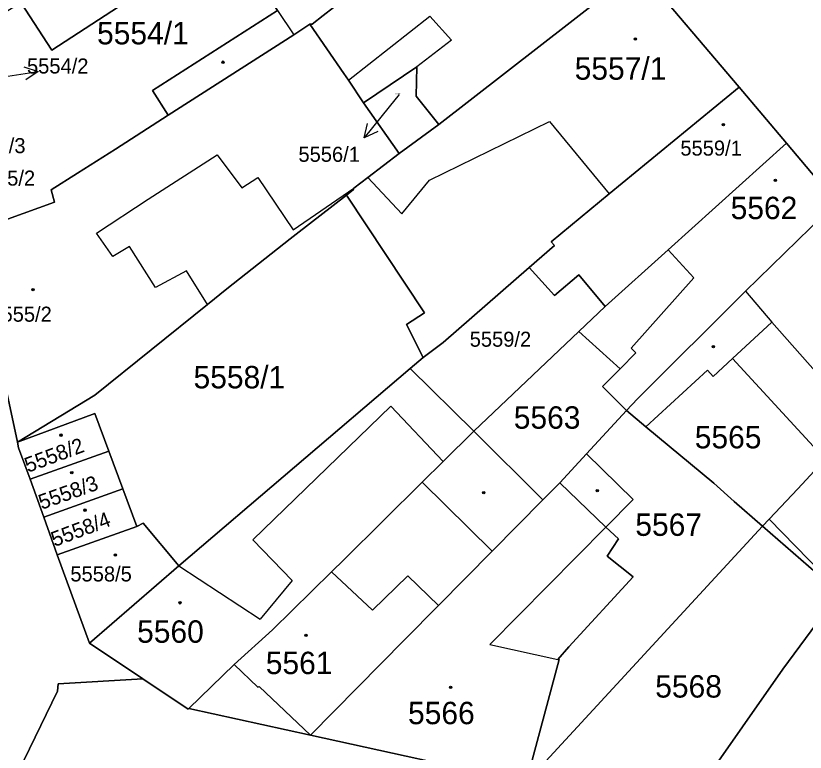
# Model space of a CAD drawing. Extents: x -596233 to -595156, y -1161235 to -1159375.
# Drawn here: x -595353.5 to -595293.6, y -1160883.5 to -1160827.6 of the extents above; entities that cross this region are included whole.
import ezdxf

# ---------------------------------------------------------------- set-up
doc = ezdxf.new("R2010")
doc.units = 0
for name, color, linetype in [('KN_CAR_KR', 7, 'Continuous'), ('KN_KULTURY', 7, 'Continuous'), ('KN_PARC_CIS_POM', 7, 'Continuous'), ('KN_PARC_CIS_POZ', 7, 'Continuous'), ('KN_PARC_CIS_STAV', 7, 'Continuous'), ('KN_PARC_PLOCHA', 7, 'Continuous'), ('PARC_C_SIPKA', 7, 'Continuous'), ('parcely_l', 7, 'Continuous')]:
    doc.layers.add(name, color=color, linetype=linetype)

msp = doc.modelspace()

# ---------------------------------------------------------------- linework, layer by layer
at = {"layer": 'KN_CAR_KR'}
for points in [[(-595333.66, -1160827.23), (-595332.43, -1160829.08)], [(-595328.27, -1160832.53), (-595322.1, -1160827.67)], [(-595322.1, -1160827.67), (-595320.45, -1160829.49)], [(-595320.45, -1160829.49), (-595323.08, -1160831.51)], [(-595322.13, -1160840.12), (-595313.02, -1160835.65)], [(-595313.02, -1160835.65), (-595308.5, -1160841.15)], [(-595343.48, -1160841.56), (-595338.23, -1160838.19)], [(-595338.23, -1160838.19), (-595336.37, -1160840.7)], [(-595336.37, -1160840.7), (-595335.14, -1160839.92)], [(-595335.14, -1160839.92), (-595332.46, -1160843.88)], [(-595326.81, -1160839.91), (-595324.22, -1160842.67)], [(-595324.22, -1160842.67), (-595322.13, -1160840.12)], [(-595332.46, -1160843.88), (-595327.86, -1160840.71)], [(-595347.39, -1160844.14), (-595343.48, -1160841.56)], [(-595346.15, -1160845.91), (-595347.39, -1160844.14)], [(-595344.88, -1160845.15), (-595346.15, -1160845.91)], [(-595342.9, -1160848.26), (-595344.88, -1160845.15)], [(-595304.02, -1160845.39), (-595302.09, -1160847.53)], [(-595340.57, -1160847), (-595342.9, -1160848.26)], [(-595338.98, -1160849.55), (-595340.57, -1160847)], [(-595302.09, -1160847.53), (-595306.84, -1160852.85)], [(-595298.16, -1160848.54), (-595296.15, -1160850.89)], [(-595299.15, -1160853.65), (-595296.15, -1160850.89)], [(-595296.15, -1160850.89), (-595289.59, -1160858.31)], [(-595307.67, -1160854.42), (-595306.47, -1160853.22)], [(-595306.47, -1160853.22), (-595306.84, -1160852.85)], [(-595325.05, -1160857.26), (-595335.54, -1160867.4)], [(-595321.09, -1160861.45), (-595325.05, -1160857.26)], [(-595322.68, -1160863.02), (-595317.37, -1160868.26)], [(-595312.24, -1160863.07), (-595308.76, -1160866.45)], [(-595291.37, -1160870.97), (-595296.37, -1160865.83)], [(-595308.76, -1160866.45), (-595317.56, -1160875.35)], [(-595335.54, -1160867.4), (-595332.54, -1160870.48)], [(-595341.13, -1160869.37), (-595334.97, -1160873.42)], [(-595329.55, -1160869.83), (-595326.44, -1160872.74)], [(-595326.44, -1160872.74), (-595323.76, -1160870.12)], [(-595323.76, -1160870.12), (-595321.44, -1160872.39)], [(-595332.54, -1160870.48), (-595334.97, -1160873.42)], [(-595317.56, -1160875.35), (-595312.39, -1160876.47)], [(-595336.95, -1160876.86), (-595335.15, -1160878.58)], [(-595335.15, -1160878.58), (-595335.06, -1160878.54)], [(-595331.16, -1160882.23), (-595335.06, -1160878.54)]]:
    msp.add_lwpolyline(points, dxfattribs=at)
at = {"layer": 'KN_KULTURY'}
for centre, radius in [((-595306.51, -1160829.41), 0.09), ((-595306.51, -1160829.41), 0.0398), ((-595337.8, -1160831.16), 0.09), ((-595337.8, -1160831.16), 0.0398), ((-595299.84, -1160835.91), 0.09), ((-595299.84, -1160835.91), 0.0398), ((-595295.89, -1160840.12), 0.09), ((-595295.89, -1160840.12), 0.0398), ((-595352.2, -1160848.42), 0.09), ((-595352.2, -1160848.42), 0.0398), ((-595300.59, -1160852.75), 0.09), ((-595300.59, -1160852.75), 0.0398), ((-595350.09, -1160859.46), 0.09), ((-595350.09, -1160859.46), 0.0398), ((-595349.26, -1160862.31), 0.09), ((-595349.26, -1160862.31), 0.0398), ((-595309.4, -1160863.66), 0.09), ((-595318.02, -1160863.82), 0.09), ((-595318.02, -1160863.82), 0.0398), ((-595309.4, -1160863.66), 0.0398), ((-595348.26, -1160865.15), 0.09), ((-595348.26, -1160865.15), 0.0398), ((-595345.95, -1160868.56), 0.09), ((-595345.95, -1160868.56), 0.0398), ((-595341.06, -1160872.18), 0.09), ((-595341.06, -1160872.18), 0.0398), ((-595331.5, -1160874.64), 0.09), ((-595331.5, -1160874.64), 0.0398), ((-595320.53, -1160878.59), 0.09), ((-595320.53, -1160878.59), 0.0398)]:
    msp.add_circle(centre, radius, dxfattribs=at)
at = {"layer": 'KN_PARC_PLOCHA'}
for points in [[(-595291.25, -1160841.8), (-595295.06, -1160837.3), (-595298.65, -1160833.06), (-595306.24, -1160824.08), (-595306.08, -1160823.95), (-595309.1, -1160820.28), (-595309.22, -1160820.38), (-595313.94, -1160814.7), (-595321.78, -1160805.34), (-595321.74, -1160805.3), (-595325.72, -1160800.55), (-595329.4, -1160796.16)], [(-595356.82, -1160844.02), (-595353.39, -1160859.98), (-595353.3, -1160860.42), (-595352.43, -1160862.81), (-595351.39, -1160865.67), (-595350.36, -1160868.53), (-595347.92, -1160875.23), (-595343.87, -1160877.94), (-595350.29, -1160878.33), (-595350.35, -1160878.88), (-595354.16, -1160886.75)], [(-595304.34, -1160890.08), (-595295.32, -1160877.21), (-595291.9, -1160872.55), (-595291.03, -1160871.54), (-595292.81, -1160869.91), (-595296.88, -1160866.37), (-595296.37, -1160865.83), (-595294.19, -1160863.52), (-595292.63, -1160861.84), (-595292.13, -1160861.26), (-595289.59, -1160858.31), (-595289.41, -1160858.1), (-595283.5, -1160850.97), (-595273.06, -1160862.41), (-595279.19, -1160870.73), (-595279.95, -1160871.75), (-595280.08, -1160871.93), (-595280.97, -1160873.16), (-595286.71, -1160881.05), (-595285, -1160882.13), (-595283.05, -1160883.35), (-595279.41, -1160885.64)], [(-595354.16, -1160886.75), (-595350.35, -1160878.88), (-595350.29, -1160878.33), (-595343.87, -1160877.94), (-595340.44, -1160880.24), (-595340.39, -1160880.2), (-595331.16, -1160882.23), (-595314.8, -1160885.82)]]:
    msp.add_lwpolyline(points, dxfattribs=at)
for points in [[(-595313.94, -1160814.7), (-595323.88, -1160822.8), (-595323.92, -1160822.74), (-595330.19, -1160827.61), (-595331.03, -1160828.27), (-595331.2, -1160828.28), (-595332.43, -1160829.08), (-595341.94, -1160835.18), (-595343.14, -1160833.31), (-595333.66, -1160827.23), (-595337.44, -1160821.55), (-595343.7, -1160825.62), (-595350.77, -1160830.25), (-595353.13, -1160826.63), (-595345.95, -1160822.04), (-595341.6, -1160819.19), (-595334.72, -1160814.69), (-595334.18, -1160814.3), (-595321.78, -1160805.34)], [(-595306.24, -1160824.08), (-595321.42, -1160835.9), (-595323.14, -1160833.75), (-595323.08, -1160831.51), (-595327.13, -1160834.25), (-595328.27, -1160832.53), (-595328.63, -1160832.01), (-595331.2, -1160828.28), (-595331.03, -1160828.27), (-595330.19, -1160827.61), (-595323.92, -1160822.74), (-595323.88, -1160822.8), (-595313.94, -1160814.7), (-595309.22, -1160820.38), (-595309.1, -1160820.28), (-595306.08, -1160823.95)], [(-595341.94, -1160835.18), (-595345.95, -1160837.75), (-595348.84, -1160839.59), (-595350.83, -1160840.85), (-595350.57, -1160841.77), (-595356.82, -1160844.02), (-595358.27, -1160844.17), (-595358.76, -1160839.37), (-595358.9, -1160835.71), (-595354.54, -1160835.03), (-595354.26, -1160834.39), (-595355.07, -1160830.1), (-595360.09, -1160831.28), (-595360.11, -1160830.94), (-595353.13, -1160826.63), (-595350.77, -1160830.25), (-595343.7, -1160825.62), (-595337.44, -1160821.55), (-595333.66, -1160827.23), (-595343.14, -1160833.31)], [(-595298.65, -1160833.06), (-595308.5, -1160841.15), (-595312.89, -1160844.78), (-595312.65, -1160845.07), (-595314.57, -1160846.74), (-595321.09, -1160852.43), (-595322.61, -1160853.56), (-595323.87, -1160851.07), (-595322.52, -1160850.18), (-595328.43, -1160841.24), (-595327.9, -1160840.83), (-595327.86, -1160840.71), (-595326.81, -1160839.91), (-595324.43, -1160838.08), (-595321.42, -1160835.9), (-595306.24, -1160824.08)], [(-595327.13, -1160834.25), (-595324.43, -1160838.08), (-595326.81, -1160839.91), (-595327.86, -1160840.71), (-595327.9, -1160840.83), (-595328.43, -1160841.24), (-595332.24, -1160844.2), (-595332.7, -1160844.56), (-595337.5, -1160848.36), (-595338.98, -1160849.55), (-595347.51, -1160856.42), (-595353.39, -1160859.98), (-595356.82, -1160844.02), (-595350.57, -1160841.77), (-595350.83, -1160840.85), (-595348.84, -1160839.59), (-595345.95, -1160837.75), (-595341.94, -1160835.18), (-595332.43, -1160829.08), (-595331.2, -1160828.28), (-595328.63, -1160832.01), (-595328.27, -1160832.53)], [(-595321.42, -1160835.9), (-595324.43, -1160838.08), (-595327.13, -1160834.25), (-595323.08, -1160831.51), (-595323.14, -1160833.75)], [(-595295.06, -1160837.3), (-595304.02, -1160845.39), (-595308.81, -1160849.71), (-595310.81, -1160847.29), (-595312.65, -1160848.87), (-595314.57, -1160846.74), (-595312.65, -1160845.07), (-595312.89, -1160844.78), (-595308.5, -1160841.15), (-595298.65, -1160833.06)], [(-595291.25, -1160841.8), (-595298.16, -1160848.54), (-595306.36, -1160856.71), (-595307.18, -1160857.59), (-595309.01, -1160855.77), (-595307.67, -1160854.42), (-595310.8, -1160851.6), (-595308.81, -1160849.71), (-595304.02, -1160845.39), (-595295.06, -1160837.3)], [(-595322.61, -1160853.56), (-595323.6, -1160854.4), (-595341.13, -1160869.37), (-595343.86, -1160866.13), (-595344.34, -1160866.4), (-595345.39, -1160863.54), (-595346.45, -1160860.67), (-595347.51, -1160857.81), (-595353.39, -1160859.98), (-595347.51, -1160856.42), (-595338.98, -1160849.55), (-595337.5, -1160848.36), (-595332.7, -1160844.56), (-595332.24, -1160844.2), (-595328.43, -1160841.24), (-595322.52, -1160850.18), (-595323.87, -1160851.07)], [(-595283.5, -1160850.97), (-595289.41, -1160858.1), (-595289.59, -1160858.31), (-595292.13, -1160861.26), (-595299.15, -1160853.65), (-595300.61, -1160855), (-595301.04, -1160854.53), (-595305.72, -1160858.84), (-595307.18, -1160857.59), (-595306.36, -1160856.71), (-595298.16, -1160848.54), (-595291.25, -1160841.8)], [(-595308.81, -1160849.71), (-595310.8, -1160851.6), (-595318.76, -1160859.16), (-595323.6, -1160854.4), (-595322.61, -1160853.56), (-595321.09, -1160852.43), (-595314.57, -1160846.74), (-595312.65, -1160848.87), (-595310.81, -1160847.29)], [(-595307.18, -1160857.59), (-595310.21, -1160860.87), (-595312.24, -1160863.07), (-595313.52, -1160864.37), (-595318.76, -1160859.16), (-595310.8, -1160851.6), (-595307.67, -1160854.42), (-595309.01, -1160855.77)], [(-595292.13, -1160861.26), (-595292.63, -1160861.84), (-595294.19, -1160863.52), (-595296.37, -1160865.83), (-595296.88, -1160866.37), (-595299.02, -1160864.48), (-595300.56, -1160863.11), (-595305.72, -1160858.84), (-595301.04, -1160854.53), (-595300.61, -1160855), (-595299.15, -1160853.65)], [(-595318.76, -1160859.16), (-595321.09, -1160861.45), (-595322.68, -1160863.02), (-595328.61, -1160868.9), (-595329.55, -1160869.83), (-595334.03, -1160874.22), (-595336.95, -1160876.86), (-595340.39, -1160880.2), (-595340.44, -1160880.24), (-595343.87, -1160877.94), (-595347.92, -1160875.23), (-595341.13, -1160869.37), (-595323.6, -1160854.4)], [(-595305.72, -1160858.84), (-595300.56, -1160863.11), (-595299.02, -1160864.48), (-595296.88, -1160866.37), (-595314.8, -1160885.82), (-595312.3, -1160876.49), (-595312.39, -1160876.47), (-595311.56, -1160875.51), (-595306.67, -1160870.22), (-595308.64, -1160868.64), (-595307.79, -1160867.33), (-595308.76, -1160866.45), (-595306.69, -1160864.35), (-595310.21, -1160860.87), (-595307.18, -1160857.59)], [(-595346.45, -1160860.67), (-595352.43, -1160862.81), (-595353.3, -1160860.42), (-595353.39, -1160859.98), (-595347.51, -1160857.81)], [(-595313.52, -1160864.37), (-595317.37, -1160868.26), (-595321.44, -1160872.39), (-595324.02, -1160875), (-595331.16, -1160882.23), (-595340.39, -1160880.2), (-595336.95, -1160876.86), (-595334.03, -1160874.22), (-595329.55, -1160869.83), (-595328.61, -1160868.9), (-595322.68, -1160863.02), (-595321.09, -1160861.45), (-595318.76, -1160859.16)], [(-595345.39, -1160863.54), (-595351.39, -1160865.67), (-595352.43, -1160862.81), (-595346.45, -1160860.67)], [(-595314.8, -1160885.82), (-595331.16, -1160882.23), (-595324.02, -1160875), (-595321.44, -1160872.39), (-595317.37, -1160868.26), (-595313.52, -1160864.37), (-595312.24, -1160863.07), (-595310.21, -1160860.87), (-595306.69, -1160864.35), (-595308.76, -1160866.45), (-595307.79, -1160867.33), (-595308.64, -1160868.64), (-595306.67, -1160870.22), (-595311.56, -1160875.51), (-595312.39, -1160876.47), (-595312.3, -1160876.49)], [(-595344.34, -1160866.4), (-595350.36, -1160868.53), (-595351.39, -1160865.67), (-595345.39, -1160863.54)], [(-595341.13, -1160869.37), (-595347.92, -1160875.23), (-595350.36, -1160868.53), (-595344.34, -1160866.4), (-595343.86, -1160866.13)], [(-595304.34, -1160890.08), (-595308.94, -1160887.69), (-595314.8, -1160885.82), (-595296.88, -1160866.37), (-595292.81, -1160869.91), (-595291.03, -1160871.54), (-595291.9, -1160872.55), (-595295.32, -1160877.21)]]:
    msp.add_lwpolyline(points, close=True, dxfattribs=at)
at = {"layer": 'PARC_C_SIPKA'}
for points in [[(-595357.15, -1160832.62), (-595354.79, -1160832.31), (-595351.8242, -1160831.8581)], [(-595352.8881, -1160831.5144), (-595351.8242, -1160831.8581), (-595352.7375, -1160832.503)], [(-595324.42, -1160833.6), (-595325.19, -1160834.56), (-595327.0762, -1160836.8929)], [(-595326.0586, -1160836.4296), (-595327.0762, -1160836.8929), (-595326.8363, -1160835.8009)]]:
    msp.add_lwpolyline(points, dxfattribs=at)
at = {"layer": 'parcely_l'}
for points in [[(-595313.94, -1160814.7), (-595323.88, -1160822.8), (-595323.92, -1160822.74), (-595330.19, -1160827.61), (-595331.03, -1160828.27), (-595331.2, -1160828.28)], [(-595341.94, -1160835.18), (-595343.14, -1160833.31), (-595333.66, -1160827.23), (-595337.44, -1160821.55), (-595343.7, -1160825.62), (-595350.77, -1160830.25), (-595353.13, -1160826.63)], [(-595306.24, -1160824.08), (-595321.42, -1160835.9)], [(-595306.24, -1160824.08), (-595298.65, -1160833.06)], [(-595341.94, -1160835.18), (-595332.43, -1160829.08), (-595331.2, -1160828.28)], [(-595331.2, -1160828.28), (-595328.63, -1160832.01), (-595328.27, -1160832.53), (-595327.13, -1160834.25)], [(-595327.13, -1160834.25), (-595323.08, -1160831.51), (-595323.14, -1160833.75), (-595321.42, -1160835.9)], [(-595314.57, -1160846.74), (-595312.65, -1160845.07), (-595312.89, -1160844.78), (-595308.5, -1160841.15), (-595298.65, -1160833.06)], [(-595298.65, -1160833.06), (-595295.06, -1160837.3)], [(-595327.13, -1160834.25), (-595324.43, -1160838.08)], [(-595356.82, -1160844.02), (-595350.57, -1160841.77), (-595350.83, -1160840.85), (-595348.84, -1160839.59), (-595345.95, -1160837.75), (-595341.94, -1160835.18)], [(-595321.42, -1160835.9), (-595324.43, -1160838.08)], [(-595295.06, -1160837.3), (-595304.02, -1160845.39), (-595308.81, -1160849.71)], [(-595295.06, -1160837.3), (-595291.25, -1160841.8)], [(-595324.43, -1160838.08), (-595326.81, -1160839.91), (-595327.86, -1160840.71), (-595327.9, -1160840.83), (-595328.43, -1160841.24)], [(-595328.43, -1160841.24), (-595332.24, -1160844.2), (-595332.7, -1160844.56), (-595337.5, -1160848.36), (-595338.98, -1160849.55), (-595347.51, -1160856.42), (-595353.39, -1160859.98)], [(-595328.43, -1160841.24), (-595322.52, -1160850.18), (-595323.87, -1160851.07), (-595322.61, -1160853.56)], [(-595307.18, -1160857.59), (-595306.36, -1160856.71), (-595298.16, -1160848.54), (-595291.25, -1160841.8)], [(-595353.39, -1160859.98), (-595356.82, -1160844.02)], [(-595322.61, -1160853.56), (-595321.09, -1160852.43), (-595314.57, -1160846.74)], [(-595308.81, -1160849.71), (-595310.81, -1160847.29), (-595312.65, -1160848.87), (-595314.57, -1160846.74)], [(-595308.81, -1160849.71), (-595310.8, -1160851.6)], [(-595310.8, -1160851.6), (-595318.76, -1160859.16)], [(-595310.8, -1160851.6), (-595307.67, -1160854.42), (-595309.01, -1160855.77), (-595307.18, -1160857.59)], [(-595323.6, -1160854.4), (-595322.61, -1160853.56)], [(-595305.72, -1160858.84), (-595301.04, -1160854.53), (-595300.61, -1160855), (-595299.15, -1160853.65), (-595292.13, -1160861.26)], [(-595341.13, -1160869.37), (-595323.6, -1160854.4)], [(-595323.6, -1160854.4), (-595318.76, -1160859.16)], [(-595310.21, -1160860.87), (-595307.18, -1160857.59)], [(-595307.18, -1160857.59), (-595305.72, -1160858.84)], [(-595346.45, -1160860.67), (-595347.51, -1160857.81), (-595353.39, -1160859.98)], [(-595318.76, -1160859.16), (-595321.09, -1160861.45), (-595322.68, -1160863.02), (-595328.61, -1160868.9), (-595329.55, -1160869.83), (-595334.03, -1160874.22), (-595336.95, -1160876.86), (-595340.39, -1160880.2)], [(-595318.76, -1160859.16), (-595313.52, -1160864.37)], [(-595305.72, -1160858.84), (-595300.56, -1160863.11), (-595299.02, -1160864.48), (-595296.88, -1160866.37)], [(-595352.43, -1160862.81), (-595353.3, -1160860.42), (-595353.39, -1160859.98)], [(-595352.43, -1160862.81), (-595346.45, -1160860.67)], [(-595346.45, -1160860.67), (-595345.39, -1160863.54)], [(-595310.21, -1160860.87), (-595306.69, -1160864.35), (-595308.76, -1160866.45), (-595307.79, -1160867.33), (-595308.64, -1160868.64), (-595306.67, -1160870.22), (-595311.56, -1160875.51), (-595312.39, -1160876.47), (-595312.3, -1160876.49), (-595314.8, -1160885.82)], [(-595313.52, -1160864.37), (-595312.24, -1160863.07), (-595310.21, -1160860.87)], [(-595292.13, -1160861.26), (-595292.63, -1160861.84), (-595294.19, -1160863.52), (-595296.37, -1160865.83), (-595296.88, -1160866.37)], [(-595351.39, -1160865.67), (-595352.43, -1160862.81)], [(-595345.39, -1160863.54), (-595351.39, -1160865.67)], [(-595344.34, -1160866.4), (-595345.39, -1160863.54)], [(-595331.16, -1160882.23), (-595324.02, -1160875), (-595321.44, -1160872.39), (-595317.37, -1160868.26), (-595313.52, -1160864.37)], [(-595350.36, -1160868.53), (-595351.39, -1160865.67)], [(-595350.36, -1160868.53), (-595344.34, -1160866.4)], [(-595344.34, -1160866.4), (-595343.86, -1160866.13), (-595341.13, -1160869.37)], [(-595296.88, -1160866.37), (-595314.8, -1160885.82)], [(-595296.88, -1160866.37), (-595292.81, -1160869.91), (-595291.03, -1160871.54), (-595291.9, -1160872.55), (-595295.32, -1160877.21), (-595304.34, -1160890.08)], [(-595347.92, -1160875.23), (-595350.36, -1160868.53)], [(-595347.92, -1160875.23), (-595341.13, -1160869.37)], [(-595343.87, -1160877.94), (-595347.92, -1160875.23)], [(-595354.16, -1160886.75), (-595350.35, -1160878.88), (-595350.29, -1160878.33), (-595343.87, -1160877.94)], [(-595343.87, -1160877.94), (-595340.44, -1160880.24), (-595340.39, -1160880.2)], [(-595340.39, -1160880.2), (-595331.16, -1160882.23)], [(-595314.8, -1160885.82), (-595331.16, -1160882.23)]]:
    msp.add_lwpolyline(points, dxfattribs=at)

# ---------------------------------------------------------------- texts
at = {"layer": 'KN_PARC_CIS_POM'}
msp.add_text('5556/1', height=0.1, dxfattribs=at).set_placement((-595324.7033, -1160833.6))
at = {"layer": 'KN_PARC_CIS_POZ'}
for s, height, p in [('5554/1', 1.7, (-595347.3466, -1160829.81)), ('5556/1', 1.14, (-595332.07, -1160838.72)), ('5535/2', 1.14, (-595356.7054, -1160840.5263)), ('5559/2', 1.14, (-595319.08, -1160852.75)), ('5558/1', 1.7, (-595340.0266, -1160855.91)), ('5563', 1.7, (-595315.7366, -1160858.97)), ('5565', 1.7, (-595302.0066, -1160860.46)), ('5567', 1.7, (-595306.5166, -1160867.1)), ('5568', 1.7, (-595305.0066, -1160879.37))]:
    msp.add_text(s, height=height, dxfattribs=at).set_placement(p)
at = {"layer": 'KN_PARC_CIS_STAV'}
for s, height, p in [('5554/2', 1.14, (-595352.66, -1160832.02)), ('5557/1', 1.7, (-595311.1166, -1160832.49)), ('5535/3', 1.14, (-595357.4342, -1160838.0619)), ('5559/1', 1.14, (-595303.1, -1160838.25)), ('5562', 1.7, (-595299.2866, -1160843.07)), ('5555/2', 1.14, (-595355.44, -1160850.85)), ('5558/5', 1.14, (-595349.37, -1160870.56)), ('5560', 1.7, (-595344.3066, -1160875.21)), ('5561', 1.7, (-595334.5466, -1160877.59)), ('5566', 1.7, (-595323.7566, -1160881.39))]:
    msp.add_text(s, height=height, dxfattribs=at).set_placement(p)
for s, rotation, p in [('5558/2', 20.46428, (-595352.5861, -1160862.3193)), ('5558/3', 19.635664, (-595351.5421, -1160865.1254)), ('5558/4', 20.682435, (-595350.5718, -1160867.9508))]:
    msp.add_text(s, height=1.14, rotation=rotation, dxfattribs=at).set_placement(p)

doc.saveas('drawing.dxf')
